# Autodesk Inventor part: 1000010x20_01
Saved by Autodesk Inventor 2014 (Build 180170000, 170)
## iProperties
Company: TraceParts S.A.
Created: 2015-09
Part Number: 1000010x20_01
Checked By: TraceParts S.A.
Catalog Web Link: www.traceparts.com
Document SubType Name: Modeling
Designer: TraceParts
Material: Générique
Density: 1 g/cm^3
Appearance: Par défaut
Author: TraceParts
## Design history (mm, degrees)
feature "1000010x20"
node "Solide1"
node "Corps solides"
node "Corps surfaciques"
